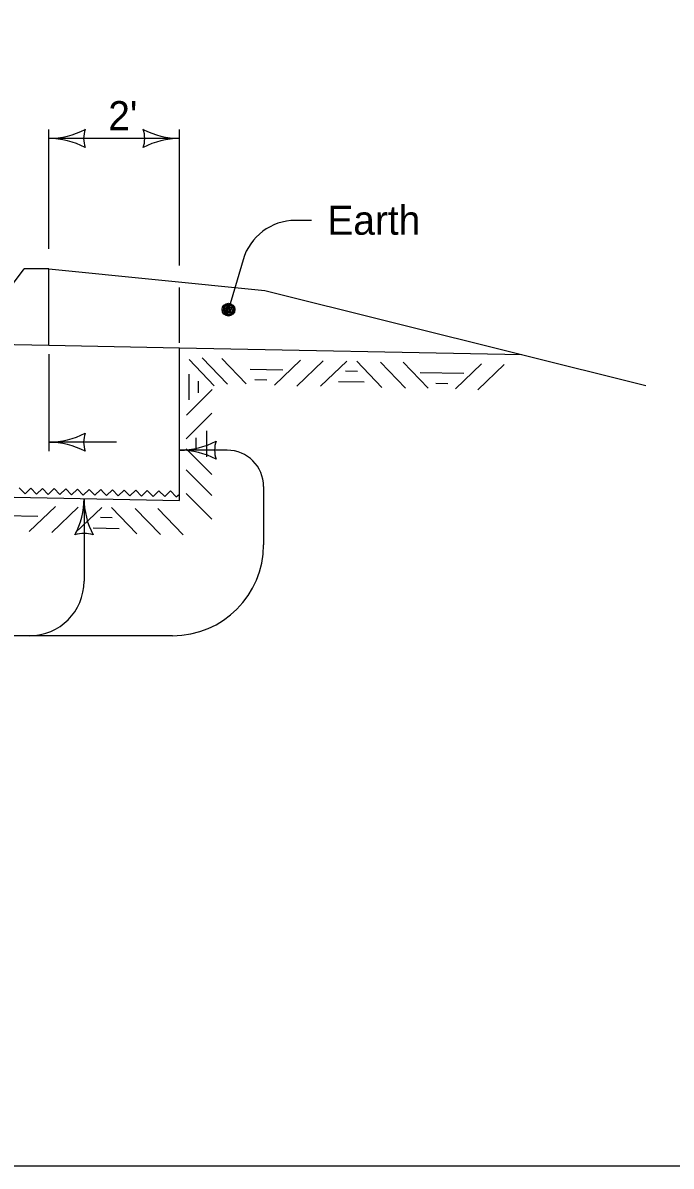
# Model space of a CAD drawing. Extents: x 10133 to 81668, y 7924 to 11018.
# Drawn here: x 11229 to 11586, y 7924 to 8553 of the extents above; entities that cross this region are included whole.
import ezdxf

# ---------------------------------------------------------------- set-up
doc = ezdxf.new("R2010")
doc.units = 0
for name, color, linetype in [('BridgeExistingStructure', 7, 'Continuous'), ('Level 2', 7, 'Continuous'), ('RasterAttachment', 7, 'Continuous'), ('SheetBorder', 7, 'Continuous')]:
    doc.layers.add(name, color=color, linetype=linetype)

msp = doc.modelspace()

# ---------------------------------------------------------------- linework, layer by layer
at = {"layer": 'Level 2'}
for p, q in [((11320.69, 8367.84), (11334.54, 8353.41)), ((11327.91, 8368.77), (11341.76, 8354.35)), ((11338.77, 8368.44), (11352.15, 8354.51)), ((11381.98, 8367.57), (11367.56, 8353.71)), ((11394.42, 8367.09), (11380, 8353.24)), ((11407.43, 8367.06), (11393.01, 8353.2)), ((11412.84, 8366.95), (11426.7, 8352.53)), ((11425.85, 8366.46), (11439.7, 8352.04)), ((11438.3, 8366.44), (11452.15, 8352.02)), ((11481.51, 8365.57), (11467.09, 8351.72)), ((11493.96, 8365.1), (11479.53, 8351.24)), ((11319.22, 8337.21), (11333.37, 8351.36)), ((11319, 8324.21), (11333.14, 8338.35)), ((11319, 8318.79), (11333.14, 8304.65)), ((11319, 8307.22), (11333.14, 8293.08)), ((11319, 8294.16), (11333.14, 8280.02))]:
    msp.add_line(p, q, dxfattribs=at)
for points in [[(11354.23, 8362.65), (11372.29, 8362.29)], [(11406.76, 8361.57), (11413.3, 8361.44)], [(11320.8, 8345.65), (11320.8, 8359.84)], [(11325.89, 8349.48), (11325.89, 8356.01)], [(11356.88, 8356.8), (11363.41, 8356.66)], [(11402.82, 8355.79), (11417.01, 8355.51)], [(11447.77, 8360.77), (11471.82, 8360.29)], [(11456.41, 8354.8), (11462.94, 8354.67)], [(11324.5, 8318.23), (11324.5, 8324.77)], [(11330.35, 8314.4), (11330.35, 8328.6)]]:
    msp.add_lwpolyline(points, dxfattribs=at)
at = {"layer": 'RasterAttachment'}
for p, q in [((11243.49, 8428.79), (11243.49, 8494.54)), ((11315.49, 8419.6), (11315.49, 8494.54)), ((11315.49, 8489.54), (11243.49, 8489.54)), ((11388.03, 8444.42), (11379.16, 8444.42)), ((11221.33, 8406.24), (11229.99, 8417.79)), ((11243.49, 8417.79), (11229.99, 8417.79)), ((11243.49, 8375.79), (11243.49, 8417.79)), ((11243.49, 8417.79), (11362.26, 8405.92)), ((11350.36, 8422.82), (11342.34, 8395.32)), ((11315.49, 8377), (11315.49, 8407.48)), ((11362.26, 8405.92), (11571.82, 8353.51)), ((10451.65, 8391.68), (11243.49, 8375.79)), ((11243.49, 8375.79), (11315.49, 8374.34)), ((11315.49, 8290.32), (11315.49, 8374.34)), ((11315.49, 8374.34), (11503.64, 8370.56)), ((11243.49, 8370.79), (11243.49, 8317.37)), ((11320.69, 8367.84), (11334.54, 8353.41)), ((11327.91, 8368.77), (11341.76, 8354.35)), ((11338.77, 8368.44), (11352.15, 8354.51)), ((11381.98, 8367.57), (11367.56, 8353.71)), ((11394.42, 8367.09), (11380, 8353.24)), ((11407.43, 8367.06), (11393.01, 8353.2)), ((11412.84, 8366.95), (11426.7, 8352.53)), ((11425.85, 8366.46), (11439.7, 8352.04)), ((11438.3, 8366.44), (11452.15, 8352.02)), ((11481.51, 8365.57), (11467.09, 8351.72)), ((11493.96, 8365.1), (11479.53, 8351.24)), ((11319.22, 8337.21), (11333.37, 8351.36)), ((11319, 8324.21), (11333.14, 8338.35)), ((11280.75, 8322.37), (11243.49, 8322.37)), ((11341.64, 8318), (11315.49, 8318)), ((11319, 8318.79), (11333.14, 8304.65)), ((10335.32, 8310), (11315.49, 8290.32)), ((11319, 8307.22), (11333.14, 8293.08)), ((11361.64, 8298), (11361.64, 8265.89)), ((11319, 8294.16), (11333.14, 8280.02)), ((11247.16, 8287.04), (11232.73, 8273.18)), ((11259.6, 8286.56), (11245.18, 8272.71)), ((11272.61, 8286.53), (11258.19, 8272.67)), ((11262.93, 8291.38), (11262.93, 8245.89)), ((11278.02, 8286.42), (11291.88, 8272)), ((11291.02, 8285.93), (11304.88, 8271.51)), ((11303.47, 8285.91), (11317.33, 8271.49)), ((11311.64, 8215.89), (11197.64, 8215.89))]:
    msp.add_line(p, q, dxfattribs=at)
for points in [[(11342.07, 8392.11), (11343.25, 8392.64), (11345.08, 8393.21), (11345.44, 8395.07), (11345.19, 8396.71), (11344.01, 8398.22), (11342.26, 8398.07), (11340.42, 8397.81), (11339.54, 8396.34), (11339.37, 8394.79), (11340.46, 8392.76), (11341.81, 8392.6), (11343.65, 8393.06), (11345.16, 8394.24), (11345.1, 8395.99), (11343.93, 8397.39), (11342.28, 8397.55), (11340.44, 8397.19), (11340.16, 8396.15), (11339.78, 8394.91), (11340.65, 8393.39), (11341.99, 8393.43), (11343.52, 8393.68), (11344.63, 8394.53), (11344.07, 8396.06), (11342.91, 8396.95), (11341.37, 8397.01), (11340.98, 8396.18), (11340.49, 8395.24), (11341.25, 8394.02), (11342.39, 8393.75), (11343.4, 8394.29), (11343.47, 8395.42), (11342.94, 8396.23), (11341.9, 8396.51), (11341.4, 8396.08), (11341.1, 8395.46), (11341.65, 8394.55), (11342.37, 8394.36), (11343.08, 8394.8), (11342.96, 8395.41), (11342.43, 8395.81), (11341.71, 8395.78), (11341.73, 8395.27), (11342.35, 8394.98)], [(11354.23, 8362.65), (11372.29, 8362.29)], [(11406.76, 8361.57), (11413.3, 8361.44)], [(11320.8, 8345.65), (11320.8, 8359.84)], [(11325.89, 8349.48), (11325.89, 8356.01)], [(11356.88, 8356.8), (11363.41, 8356.66)], [(11402.82, 8355.79), (11417.01, 8355.51)], [(11447.77, 8360.77), (11471.82, 8360.29)], [(11456.41, 8354.8), (11462.94, 8354.67)], [(11324.5, 8318.23), (11324.5, 8324.77)], [(11330.35, 8314.4), (11330.35, 8328.6)], [(11227.33, 8297.22), (11230.46, 8293.95), (11233.73, 8297.09), (11236.86, 8293.82), (11240.13, 8296.96), (11243.26, 8293.69), (11246.52, 8296.83), (11249.66, 8293.57), (11252.92, 8296.7), (11256.06, 8293.44), (11259.32, 8296.57), (11262.46, 8293.31), (11265.72, 8296.44), (11268.86, 8293.18), (11272.12, 8296.32), (11273.69, 8294.68)], [(11273.69, 8294.68), (11275.25, 8293.05), (11278.52, 8296.19), (11281.65, 8292.92), (11284.92, 8296.06), (11288.05, 8292.8), (11291.32, 8295.93), (11294.45, 8292.67), (11297.71, 8295.8), (11300.85, 8292.54), (11304.11, 8295.67), (11307.25, 8292.41), (11310.51, 8295.55), (11313.65, 8292.28), (11315.49, 8293.85)], [(11219.4, 8282.12), (11237.47, 8281.76)], [(11271.94, 8281.04), (11278.47, 8280.91)], [(11267.99, 8275.27), (11282.18, 8274.98)]]:
    msp.add_lwpolyline(points, dxfattribs=at)
msp.add_circle((11342.34, 8395.32), 3.5, dxfattribs=at)
for centre, radius, start, end in [((11243.49, 8532.04), 42.5, 270, 298.07249), ((11243.49, 8532.04), 42.5, 270, 298.07249), ((11279.13, 8489.54), 16.42, 162.26665, 197.73335), ((11279.13, 8489.54), 16.42, 162.26665, 197.73335), ((11279.86, 8489.54), 16.42, 342.26665, 17.73335), ((11315.49, 8532.04), 42.5, 241.92751, 270), ((11279.86, 8489.54), 16.42, 342.26665, 17.73335), ((11315.49, 8532.04), 42.5, 241.92751, 270), ((11243.49, 8447.04), 42.5, 61.92751, 90), ((11243.49, 8447.04), 42.5, 61.92751, 90), ((11315.49, 8447.04), 42.5, 90, 118.07249), ((11315.49, 8447.04), 42.5, 90, 118.07249), ((11379.16, 8414.42), 30, 90, 163.73903), ((11243.49, 8364.87), 42.5, 270, 298.07249), ((11243.49, 8364.87), 42.5, 270, 298.07249), ((11279.13, 8322.37), 16.42, 162.26665, 197.73335), ((11279.13, 8322.37), 16.42, 162.26665, 197.73335), ((11243.49, 8279.87), 42.5, 61.92751, 90), ((11243.49, 8279.87), 42.5, 61.92751, 90), ((11315.49, 8360.5), 42.5, 270, 298.07249), ((11315.49, 8360.5), 42.5, 270, 298.07249), ((11315.49, 8275.5), 42.5, 61.92751, 90), ((11315.49, 8275.5), 42.5, 61.92751, 90), ((11351.13, 8318), 16.42, 162.26665, 197.73335), ((11351.13, 8318), 16.42, 162.26665, 197.73335), ((11341.64, 8298), 20, 0, 90), ((11220.43, 8291.38), 42.5, 331.92751, 360), ((11220.43, 8291.38), 42.5, 331.92751, 360), ((11305.43, 8291.38), 42.5, 180, 208.07249), ((11305.43, 8291.38), 42.5, 180, 208.07249), ((11262.93, 8255.74), 16.42, 72.26665, 107.73335), ((11262.93, 8255.74), 16.42, 72.26665, 107.73335), ((11311.64, 8265.89), 50, 270, 360), ((11232.93, 8245.89), 30, 270, 360)]:
    msp.add_arc(centre, radius, start, end, dxfattribs=at)
at = {"layer": 'SheetBorder'}
msp.add_lwpolyline([(10132.52, 9944.02), (13267.53, 9944.02), (13267.53, 7924.02), (10132.52, 7924.02)], close=True, dxfattribs=at)

# ---------------------------------------------------------------- texts
at = {"layer": 'BridgeExistingStructure'}
for s, p in [("2'", (11276.24, 8494.06)), ('Earth', (11396.69, 8436.54))]:
    msp.add_text(s, height=16, dxfattribs=at).set_placement(p)

doc.saveas('drawing.dxf')
